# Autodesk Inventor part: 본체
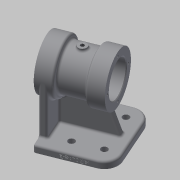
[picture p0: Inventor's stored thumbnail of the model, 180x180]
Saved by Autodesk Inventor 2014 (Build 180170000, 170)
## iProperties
Created: 2020-06
Part Number: 본체
Material: Generic
Document SubType Name: Modeling
Designer: kh
Density: 1 g/cm^3
Appearance: Default
Mass: 264.289 g
Surface Area: 646.01 cm^2
Volume: 264.289 cm^3
Author: kh
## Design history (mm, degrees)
sketch "Sketch1"
  geometry: L1 (-49, 45)-(49, 45); L2 (49, 45)-(49, -45); L3 (49, -45)-(-49, -45); L4 (-49, -45)-(-49, 45); L5 (-49, 45)-(49, -45); L6 (49, 45)-(-49, -45); 1 further point
  constraints: 12 end point, 2 midpoint, 2 parallel, 1 horizontal, 1 perpendicular
  dimensions: "d0" = 98 distance of L2.end L3.end; "d1" = 90 distance of L1.end L2.end
extrude "Extrusion1" new body sketch "Sketch1" distance "d2" = 10; taper "d3" = 0 deg
workplane "Work Plane2"
sketch "Sketch2"
  geometry: L1 (-29, 80)-(141, 80); L2 (0, 0)-(90, 0) reference; L3 (-5, 115)-(-5, 80); L4 (0, 0)-(0, 10) reference; L5 (-5, 115)-(17, 115); L6 (73, 115)-(73, 80); L7 (73, 115)-(51, 115); L8 (17, 109)-(51, 109); L9 (17, 115)-(17, 109); L10 (51, 115)-(51, 109); L11 (34, 109)-(34, 80); 1 further point
  constraints: 18 end point, 7 perpendicular, 3 point on line, 1 horizontal, 1 midpoint, 1 parallel
  dimensions: "d5" = 80 distance between parallel lines of L2 L1; "d6" = 5 distance between parallel lines of L4 L3; "d7" = 22 distance of L3.start L5.end; "d8" = 70 diameter of L5 L1; "d9" = 78 distance between parallel lines of L6 L3; "d10" = 22 distance of L6.start L7.end; "d11" = 70 diameter of L7 L1 (= d8); "d12" = 58 diameter of L8 L1
revolve "Revolution1" sketch "Sketch2" stored, may be unused: angle "d13" = 90 deg
sketch "Sketch4"
  geometry: L1 (0, 0)-(90, 0) reference; L2 (0, 0)-(0, 10) reference; L3 (90, 10)-(0, 10) reference; L4 (90, 0)-(90, 10) reference; L5 (51, 45)-(73, 45) reference; L6 (-5, 45)-(17, 45) reference; L7 (0, 10)-(0, 63); L8 (78, 10)-(61.493, 55.354); L9 (61.493, 55.354)-(0, 63); L10 (78, 10)-(0, 10); 1 further point
  constraints: 8 end point, 2 perpendicular, 1 point on line
  dimensions: "d17" = 70 deg angle of L3 L8; "d18" = 12 distance from line of L4 L8.start
extrude "Extrusion2" join sketch "Sketch4" stored distance "d19" = 10; taper "d20" = 0 deg
sketch "Sketch5"
  geometry: L1 (0, 0)-(0, 10) reference; L2 (14, 80)-(14, 5); L3 (84, 80)-(84, 5); L4 (84, 5)-(14, 5); L5 (14, 80)-(84, 80); A1 r 35 centre (49, 80) between (14, 80) and (84, 80) reference; 1 further point
  constraints: 8 end point, 2 parallel, 2 perpendicular, 2 point on circle, 2 tangent
extrude "Extrusion3" join sketch "Sketch5" distance "d21" = 10; taper "d22" = 0 deg
workplane "Work Plane4"
  workplane "Work Plane3"
sketch "Sketch7"
  geometry: L1 (-35, 39)-(35, 39) reference; L2 (-35, -39)-(35, -39) reference; L3 (0, 39)-(0, -39); C1 r 6 at (0, 0); 1 further point
  constraints: 3 midpoint, 2 end point, 1 centre point
  dimensions: "d27" = 12 diameter of C1
extrude "Extrusion5" join sketch "Sketch7" distance "d28" = 5; taper "d29" = 0 deg
sketch "Sketch8"
  geometry: L1 (45, 50)-(115, 50) reference; L2 (45, -28)-(115, -28) reference; L3 (80, -28)-(80, 50); L4 (103.5, 50)-(103.5, 32); L5 (103.5, 32)-(100, 32); L6 (100, 32)-(100, 26); L7 (104, 26)-(104, -4); L8 (100, 26)-(104, 26); L9 (104, -4)-(100, -4); L10 (100, -4)-(100, -10); L11 (100, -10)-(103.5, -10); L12 (103.5, -10)-(103.5, -28); L13 (103.5, -28)-(80, -28); L14 (103.5, 50)-(80, 50); 1 further point
  constraints: 24 end point, 5 parallel, 4 perpendicular, 2 collinear, 2 midpoint, 2 point on line
  dimensions: "d31" = 47 diameter of L4 L3; "d32" = 18 distance of L4.start L4.end; "d33" = 6 distance of L5.end L6.end; "d34" = 48 diameter of L7 L3; "d35" = 47 diameter of L12 L3 (= d31); "d36" = 6 distance between parallel lines of L9 L11; "d37" = 40 diameter of L10 L3; "d38" = 40 diameter of L6 L3 (= d37); "d39" = 18 distance between parallel lines of L2 L11 (= d32)
revolve "Revolution2" sketch "Sketch8" stored, may be unused: angle "d40" = 90 deg
sketch "Sketch9"
  geometry: C1 r 35 at (0, 0) reference; A1 r 28.5 centre (0, 0) between (0, 28.5) and (28.5, 0); 3 further points
  constraints: 4 point on circle, 1 centre point, 1 coincident
  dimensions: "d41" = 57 diameter of A1
hole "Hole1" sketch "Sketch9" at (0, 28.5), (28.5, 0), (-28.5, 0), (0, -28.5) diameter "d42" = 3.242; stored, may be unused: countersink angle "d46" = 90 deg, drill point angle "d48" = 118 deg; dims "d43" = 10, "d44" = 4, "d45" = 2, "d47" = 12
workplane "Work Plane5"
mirror "Mirror1"
sketch "Sketch10"
  geometry: L1 (49, -45)-(-49, -45) reference; L2 (0, -45)-(0, 45); L3 (-49, 45)-(49, 45) reference; 5 further points
  constraints: 2 end point, 2 midpoint, 2 symmetric about line, 1 perpendicular, 1 vertical alignment
  dimensions: "d49" = 36 distance of point (-29, 25) point (-29, -11); "d50" = 70 distance from line of L1 point (-29, 25); "d51" = 29 distance from line of L2 point (-29, 25)
hole "Hole2" sketch "Sketch10" at (-29, -11), (-29, 25), (29, 25), (29, -11) diameter "d52" = 9; stored, may be unused: countersink angle "d56" = 90 deg, drill point angle "d58" = 118 deg; dims "d53" = 10, "d54" = 4, "d55" = 2, "d57" = 12
hole "Hole3" diameter "d61" = 5.188; stored, may be unused: countersink angle "d65" = 90 deg, drill point angle "d67" = 118 deg; dims "d59" = 10, "d60" = 10, "d62" = 20, "d63" = 4, "d64" = 2, "d66" = 25
fillet "Fillet1" dims "d68" = 3
fillet "Fillet2" dims "d69" = 3
fillet "Fillet3" dims "d70" = 3
fillet "Fillet4" dims "d71" = 3
fillet "Fillet5" dims "d72" = 3, "d73" = 0.3
chamfer "Chamfer1" distance "d74" = 1; stored, may be unused: second distance "d75" = 2, angle "d76" = 45 deg
fillet "Fillet6" dims "d77" = 20
fillet "Fillet7" dims "d78" = 3
sketch "Sketch11"
  geometry: L1 (67, 0)-(0, 0) reference; L2 (-3, 7)-(-3, 0) reference; 2 further points
  constraints: 1 other
  dimensions: "d79" = 45 distance from line of L2 point (42, 4); "d80" = 4 distance from line of L1 point (42, 4)
emboss "Emboss1" sketch "Sketch11" dims "d0" = 98, "d1" = 90, "d11" = 70 (= d8), "d81" = 0.5, "d82" = 0
body "Solid1"
node "Projected Loop1"
node "Projected Loop2"
other parameters: "d26" = 3
